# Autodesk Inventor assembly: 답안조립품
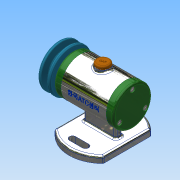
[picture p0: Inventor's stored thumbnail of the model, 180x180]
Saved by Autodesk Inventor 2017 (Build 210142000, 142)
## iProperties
Part Number: 답안조립품
Material: 일반
Document SubType Name: Assembly
Designer: user
Author: user
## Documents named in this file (14)
- C:\Users\user\Desktop\710906V1029\답안조립품.iam
- C:\Users\user\Desktop\710906V1029\본체.ipt
- C:\Users\user\Desktop\710906V1029\앞커버.ipt
- C:\Users\user\Desktop\710906V1029\뒤커버.ipt
- C:\Users\user\Desktop\710906V1029\오일 실 15x25x7.ipt
- C:\Users\user\Desktop\710906V1029\베어링 15x32x9.ipt
- C:\Users\user\Desktop\710906V1029\축.ipt
- C:\Users\user\Desktop\710906V1029\키 3x3.ipt
- C:\Users\user\Desktop\710906V1029\V벨트풀리.ipt
- C:\Users\user\Desktop\710906V1029\와셔 8x17.ipt
- C:\Users\user\Desktop\710906V1029\스프링와셔 8.ipt
- C:\Users\user\Desktop\710906V1029\너트 M8.ipt
- C:\Users\user\Desktop\710906V1029\캡.ipt
- C:\Users\user\Desktop\710906V1029\볼트 M4x12.ipt
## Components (1 placed, 1 different names)
1. V벨트풀리:1
